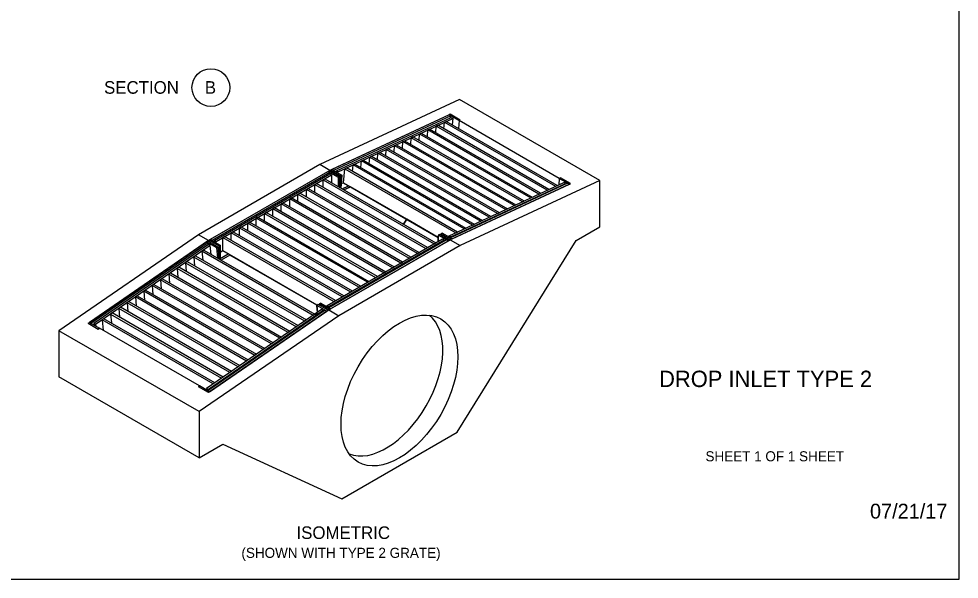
# Model space of a CAD drawing. Extents: x 99862 to 103151, y 100000 to 102076.
# Drawn here: x 101658 to 103151, y 100000 to 100890 of the extents above; entities that cross this region are included whole.
import ezdxf

# ---------------------------------------------------------------- set-up
doc = ezdxf.new("R2010")
doc.units = 0
for name, color, linetype in [('Level 1', 7, 'Continuous'), ('Level 10', 7, 'Continuous'), ('Level 15', 7, 'Continuous'), ('Level 2', 7, 'Continuous'), ('Level 20', 7, 'Continuous'), ('Level 4', 7, 'Continuous'), ('Level 62', 7, 'Continuous'), ('Level 7', 7, 'Continuous'), ('Level 9', 7, 'Continuous')]:
    doc.layers.add(name, color=color, linetype=linetype)

msp = doc.modelspace()

# ---------------------------------------------------------------- linework, layer by layer
at = {"layer": 'Level 1'}
msp.add_lwpolyline([(99862, 99999.5), (103151, 99999.5), (103151, 102075.5), (99862, 102075.5)], close=True, dxfattribs=at)
at = {"layer": 'Level 10'}
for points in [[(102269, 100563.5), (102274, 100571.5), (102184.7, 100623), (102174.3, 100618.1), (102269, 100563.5)], [(102274, 100571.5), (102269, 100563.5), (102320.1, 100534), (102324.1, 100536.3), (102324.1, 100542.5), (102274, 100571.5)], [(102132.1, 100423.4), (102131.2, 100434.5), (102131.4, 100434.7), (101993.3, 100514.4), (101979.2, 100506.3), (102127.9, 100420.5), (102132.1, 100423.4)]]:
    msp.add_lwpolyline(points, dxfattribs=at)
at = {"layer": 'Level 2'}
for p, q in [((102341.2, 100737.3), (102155.1, 100650.4)), ((102343.8, 100735.7), (102157.7, 100648.8)), ((102343.1, 100738.2), (102341.2, 100737.3)), ((102343.8, 100735.7), (102341.2, 100737.3)), ((102359, 100729), (102343.1, 100738.2)), ((102343.6, 100732.9), (102343.8, 100735.7)), ((102357.1, 100728.1), (102359, 100729)), ((102149.1, 100647.3), (101962.1, 100539.3)), ((102151.7, 100645.7), (101964.8, 100537.8)), ((102149.1, 100647.3), (102151.1, 100648.4)), ((102151.7, 100645.7), (102149.1, 100647.3)), ((102151.7, 100643.4), (102151.7, 100645.7)), ((102152.9, 100647.3), (102153.1, 100649.5)), ((102153.1, 100649.5), (102155.1, 100650.4)), ((102157.7, 100648.8), (102155.1, 100650.4)), ((102167, 100639.2), (102165, 100638.1)), ((102171, 100641.2), (102169, 100640.3)), ((102518.1, 100637.1), (102516.2, 100636.2)), ((102171.4, 100619.8), (102181.7, 100624.7)), ((102174.3, 100618.1), (102184.7, 100623)), ((102529.4, 100628.6), (102343.3, 100541.7)), ((102346, 100540.2), (102532.1, 100627)), ((102529.4, 100628.6), (102532.1, 100627)), ((102532.1, 100627), (102534.1, 100628)), ((102330.1, 100549.3), (102328.1, 100548.4)), ((102346, 100540.2), (102330.1, 100549.3)), ((101770.1, 100407.5), (101956.1, 100535.5)), ((101958.8, 100534), (101772.7, 100406)), ((101956.1, 100535.5), (101958.1, 100536.9)), ((101958.8, 100534), (101956.1, 100535.5)), ((101959.1, 100530.8), (101958.8, 100534)), ((101960.1, 100538.2), (101962.1, 100539.3)), ((101960.1, 100535.7), (101960.1, 100538.2)), ((101964.8, 100537.8), (101962.1, 100539.3)), ((102337.3, 100538.6), (102150.4, 100430.6)), ((102153.1, 100429.1), (102340, 100537)), ((102326.1, 100547.4), (102324.1, 100546.2)), ((102342, 100538.2), (102326.1, 100547.4)), ((102337.3, 100538.6), (102340, 100537)), ((102340, 100537), (102342, 100538.2)), ((102343.3, 100541.7), (102346, 100540.2)), ((102346, 100540.2), (102344, 100539.2)), ((101972.1, 100526.3), (101974, 100527.7)), ((101978, 100530.1), (101976.1, 100529)), ((101990.6, 100516), (101978, 100508.7)), ((101978, 100507), (101978, 100508.7)), ((101993.3, 100514.4), (101979.2, 100506.3)), ((102133.1, 100435.9), (102131.2, 100434.5)), ((102149, 100426.7), (102133.1, 100435.9)), ((102135.2, 100437.1), (102137.1, 100438.3)), ((102153.1, 100429.1), (102137.1, 100438.3)), ((102150.4, 100430.6), (102153.1, 100429.1)), ((102151.1, 100427.9), (102153.1, 100429.1)), ((102144.4, 100426.8), (101958.3, 100298.8)), ((101961, 100297.3), (102147.1, 100425.3)), ((102144.4, 100426.8), (102147.1, 100425.3)), ((102147.1, 100425.3), (102149, 100426.7)), ((101768.1, 100406.2), (101770.1, 100407.5)), ((101768.1, 100406.2), (101784, 100397)), ((101772.7, 100406), (101770.1, 100407.5)), ((101770.1, 100407.5), (101786, 100398.3)), ((101784, 100397), (101786, 100398.3)), ((101945.1, 100306.5), (101943.1, 100305.1)), ((101959, 100295.9), (101943.1, 100305.1)), ((101961, 100297.3), (101945.1, 100306.5)), ((101958.3, 100298.8), (101961, 100297.3)), ((101961, 100297.3), (101959, 100295.9))]:
    msp.add_line(p, q, dxfattribs=at)
for points in [[(102341.2, 100737.3), (102357.1, 100728.1), (102356.1, 100715.6)], [(102149.1, 100647.3), (102165, 100638.1), (102165, 100623.5)], [(102151.1, 100648.4), (102167, 100639.2), (102167, 100622.4)], [(102153.1, 100649.5), (102169, 100640.3), (102167.6, 100622)], [(102155.1, 100650.4), (102171, 100641.2), (102169.4, 100621)], [(102534.1, 100628), (102518.1, 100637.1)], [(102516.2, 100636.2), (102515.4, 100626.2)], [(102532.1, 100627), (102516.2, 100636.2)], [(102344, 100539.2), (102328.1, 100548.4), (102327.9, 100546.3)], [(101956.1, 100535.5), (101972.1, 100526.3), (101973.5, 100509.6)], [(101958.1, 100536.9), (101974, 100527.7), (101975.7, 100508.4)], [(101960.1, 100538.2), (101976.1, 100529), (101976.1, 100508.2)], [(101962.1, 100539.3), (101978, 100530.1), (101978, 100507)], [(102340, 100537), (102324.1, 100546.2), (102324.1, 100536.3)], [(102147.1, 100425.3), (102131.2, 100434.5), (102132.1, 100423.4)], [(102151.1, 100427.9), (102135.2, 100437.1), (102135.2, 100434.7)]]:
    msp.add_lwpolyline(points, dxfattribs=at)
at = {"layer": 'Level 4'}
for p, q in [((102162.3, 100648.2), (102344.5, 100733.3)), ((102333.9, 100725.6), (102336.6, 100726.8)), ((102512.9, 100625), (102336.6, 100726.8)), ((102344.5, 100733.3), (102347.1, 100731.7)), ((102306.7, 100702.7), (102307.5, 100713.3)), ((102307.5, 100713.3), (102310.2, 100714.5)), ((102483.9, 100611.5), (102307.5, 100713.3)), ((102486.5, 100612.7), (102310.2, 100714.5)), ((102319.9, 100708.9), (102320.7, 100719.4)), ((102320.7, 100719.4), (102323.4, 100720.7)), ((102497.1, 100617.6), (102320.7, 100719.4)), ((102499.7, 100618.8), (102323.4, 100720.7)), ((102333.1, 100715), (102333.9, 100725.6)), ((102333.9, 100725.6), (102510.3, 100623.8)), ((102280.3, 100690.4), (102281.1, 100700.9)), ((102281.1, 100700.9), (102283.8, 100702.2)), ((102457.5, 100599.1), (102281.1, 100700.9)), ((102460.1, 100600.4), (102283.8, 100702.2)), ((102293.5, 100696.6), (102294.3, 100707.1)), ((102294.3, 100707.1), (102297, 100708.3)), ((102294.3, 100707.1), (102470.7, 100605.3)), ((102297, 100708.3), (102473.3, 100606.5)), ((102240.7, 100671.9), (102241.5, 100682.4)), ((102241.5, 100682.4), (102244.2, 100683.7)), ((102417.9, 100580.6), (102241.5, 100682.4)), ((102244.2, 100683.7), (102420.5, 100581.9)), ((102253.9, 100678.1), (102254.7, 100688.6)), ((102254.7, 100688.6), (102257.4, 100689.8)), ((102254.7, 100688.6), (102431.1, 100586.8)), ((102257.4, 100689.8), (102433.7, 100588)), ((102267.1, 100684.2), (102267.9, 100694.8)), ((102267.9, 100694.8), (102270.6, 100696)), ((102444.3, 100593), (102267.9, 100694.8)), ((102270.6, 100696), (102446.9, 100594.2)), ((102214.3, 100659.6), (102215.2, 100670.1)), ((102215.2, 100670.1), (102217.8, 100671.4)), ((102215.2, 100670.1), (102391.5, 100568.3)), ((102217.8, 100671.4), (102394.1, 100569.6)), ((102227.5, 100665.7), (102228.3, 100676.3)), ((102228.3, 100676.3), (102231, 100677.5)), ((102404.7, 100574.5), (102228.3, 100676.3)), ((102407.3, 100575.7), (102231, 100677.5)), ((102175.6, 100651.6), (102178.2, 100652.9)), ((102354.5, 100551.1), (102178.2, 100652.9)), ((102187.9, 100647.3), (102188.8, 100657.8)), ((102188.8, 100657.8), (102191.4, 100659)), ((102365.1, 100556), (102188.8, 100657.8)), ((102191.4, 100659), (102367.7, 100557.2)), ((102201.1, 100653.4), (102202, 100664)), ((102202, 100664), (102204.6, 100665.2)), ((102378.3, 100562.2), (102202, 100664)), ((102204.6, 100665.2), (102380.9, 100563.4)), ((101968.8, 100537.8), (102151.7, 100643.4)), ((102154.4, 100641.9), (102151.7, 100643.4)), ((102162.2, 100646.3), (102162.3, 100648.2)), ((102165, 100646.7), (102162.3, 100648.2)), ((102164.8, 100644.7), (102165, 100646.7)), ((102173.8, 100629.3), (102175.6, 100651.6)), ((102175.6, 100651.6), (102351.9, 100549.8)), ((102127.9, 100626.6), (102130.5, 100628.1)), ((102127.9, 100614.3), (102127.9, 100626.6)), ((102127.9, 100626.6), (102304.2, 100524.8)), ((102306.8, 100526.3), (102130.5, 100628.1)), ((102141.1, 100634.2), (102143.8, 100635.8)), ((102141.1, 100622), (102141.1, 100634.2)), ((102141.1, 100634.2), (102317.5, 100532.4)), ((102143.8, 100635.8), (102320.1, 100534)), ((102173.8, 100629.3), (102169.9, 100627.5)), ((102173.8, 100629.3), (102324.1, 100542.5)), ((102341.3, 100544.9), (102523.5, 100629.9)), ((102510.3, 100623.8), (102512.9, 100625)), ((102526.1, 100628.4), (102523.5, 100629.9)), ((102101.3, 100611.3), (102104, 100612.8)), ((102101.3, 100599), (102101.3, 100611.3)), ((102101.3, 100611.3), (102277.7, 100509.5)), ((102280.3, 100511), (102104, 100612.8)), ((102114.6, 100618.9), (102117.3, 100620.5)), ((102114.6, 100606.7), (102114.6, 100618.9)), ((102290.9, 100517.1), (102114.6, 100618.9)), ((102117.3, 100620.5), (102293.6, 100518.7)), ((102483.9, 100611.5), (102486.5, 100612.7)), ((102497.1, 100617.6), (102499.7, 100618.8)), ((102074.8, 100596), (102077.5, 100597.5)), ((102074.8, 100583.7), (102074.8, 100596)), ((102251.2, 100494.2), (102074.8, 100596)), ((102077.5, 100597.5), (102253.8, 100495.7)), ((102088.1, 100603.6), (102090.7, 100605.2)), ((102088.1, 100591.4), (102088.1, 100603.6)), ((102264.4, 100501.8), (102088.1, 100603.6)), ((102267.1, 100503.3), (102090.7, 100605.2)), ((102444.3, 100593), (102446.9, 100594.2)), ((102457.5, 100599.1), (102460.1, 100600.4)), ((102470.7, 100605.3), (102473.3, 100606.5)), ((102048.3, 100580.7), (102051, 100582.2)), ((102048.3, 100568.4), (102048.3, 100580.7)), ((102048.3, 100580.7), (102224.6, 100478.8)), ((102227.3, 100480.4), (102051, 100582.2)), ((102061.6, 100588.3), (102064.2, 100589.8)), ((102061.6, 100576.1), (102061.6, 100588.3)), ((102061.6, 100588.3), (102237.9, 100486.5)), ((102064.2, 100589.8), (102240.6, 100488)), ((102417.9, 100580.6), (102420.5, 100581.9)), ((102431.1, 100586.8), (102433.7, 100588)), ((102021.8, 100565.3), (102024.4, 100566.9)), ((102021.8, 100553.1), (102021.8, 100565.3)), ((102198.1, 100463.5), (102021.8, 100565.3)), ((102200.8, 100465.1), (102024.4, 100566.9)), ((102035.1, 100573), (102037.7, 100574.5)), ((102035.1, 100560.8), (102035.1, 100573)), ((102211.4, 100471.2), (102035.1, 100573)), ((102037.7, 100574.5), (102214, 100472.7)), ((102378.3, 100562.2), (102380.9, 100563.4)), ((102391.5, 100568.3), (102394.1, 100569.6)), ((102404.7, 100574.5), (102407.3, 100575.7)), ((101995.3, 100550), (101997.9, 100551.6)), ((101995.3, 100537.8), (101995.3, 100550)), ((102171.6, 100448.2), (101995.3, 100550)), ((102174.3, 100449.8), (101997.9, 100551.6)), ((102008.5, 100557.7), (102011.2, 100559.2)), ((102008.5, 100545.4), (102008.5, 100557.7)), ((102008.5, 100557.7), (102184.9, 100455.9)), ((102011.2, 100559.2), (102187.5, 100457.4)), ((102351.9, 100549.8), (102354.5, 100551.1)), ((102365.1, 100556), (102367.7, 100557.2)), ((101968.8, 100535.5), (101968.8, 100537.8)), ((101968.8, 100537.8), (101971.4, 100536.3)), ((101971.4, 100534), (101971.4, 100536.3)), ((101982, 100542.4), (101984.7, 100543.9)), ((101982, 100542.4), (102158.4, 100440.6)), ((101982, 100521), (101982, 100542.4)), ((102161, 100442.1), (101984.7, 100543.9)), ((102147.7, 100434.5), (102330.7, 100540.1)), ((102317.5, 100532.4), (102320.1, 100534)), ((102330.7, 100540.1), (102333.4, 100538.6)), ((102341.2, 100542.9), (102341.3, 100544.9)), ((102344, 100543.4), (102341.3, 100544.9)), ((102343.9, 100541.9), (102344, 100543.4)), ((102125.3, 100418.7), (101948.9, 100520.5)), ((101951.6, 100522.3), (102127.9, 100420.5)), ((101962.1, 100529.6), (101959.5, 100531.1)), ((101963.3, 100515.5), (101962.1, 100529.6)), ((101982, 100521), (101978, 100518.7)), ((102131.4, 100434.7), (101982, 100521)), ((102290.9, 100517.1), (102293.6, 100518.7)), ((102304.2, 100524.8), (102306.8, 100526.3)), ((101925.2, 100504.2), (102101.5, 100402.4)), ((102112.1, 100409.6), (101935.7, 100511.4)), ((101938.4, 100513.2), (102114.7, 100411.4)), ((102264.4, 100501.8), (102267.1, 100503.3)), ((102277.7, 100509.5), (102280.3, 100511)), ((102085.7, 100391.5), (101909.3, 100493.3)), ((102088.3, 100393.3), (101912, 100495.1)), ((101922.5, 100502.3), (102098.9, 100400.5)), ((102237.9, 100486.5), (102240.6, 100488)), ((102251.2, 100494.2), (102253.8, 100495.7)), ((102059.3, 100373.3), (101882.9, 100475.1)), ((102061.9, 100375.1), (101885.6, 100476.9)), ((102072.5, 100382.4), (101896.1, 100484.2)), ((101898.8, 100486), (102075.1, 100384.2)), ((102224.6, 100478.8), (102227.3, 100480.4)), ((101859.2, 100458.8), (102035.5, 100357)), ((102046.1, 100364.2), (101869.7, 100466)), ((101872.4, 100467.8), (102048.7, 100366)), ((102198.1, 100463.5), (102200.8, 100465.1)), ((102211.4, 100471.2), (102214, 100472.7)), ((102019.7, 100346.1), (101843.3, 100447.9)), ((101846, 100449.7), (102022.3, 100347.9)), ((102032.9, 100355.1), (101856.5, 100457)), ((102171.6, 100448.2), (102174.3, 100449.8)), ((102184.9, 100455.9), (102187.5, 100457.4)), ((101993.3, 100327.9), (101816.9, 100429.7)), ((101995.9, 100329.7), (101819.6, 100431.5)), ((102006.5, 100337), (101830.1, 100438.8)), ((101832.8, 100440.6), (102009.1, 100338.8)), ((102147.7, 100432.2), (102147.7, 100434.5)), ((102147.7, 100434.5), (102150.4, 100432.9)), ((102150.4, 100430.6), (102150.4, 100432.9)), ((102158.4, 100440.6), (102161, 100442.1)), ((101969.5, 100311.6), (101793.2, 100413.4)), ((101803.7, 100420.6), (101980.1, 100318.8)), ((101982.7, 100320.7), (101806.4, 100422.5)), ((102127.9, 100420.5), (102125.3, 100418.7)), ((102138.5, 100427.8), (102141.1, 100426.2)), ((102141.2, 100424.7), (102141.1, 100426.2)), ((101780, 100404.3), (101777.3, 100405.8)), ((101966.9, 100309.8), (101790.5, 100411.6)), ((102101.5, 100402.4), (102098.9, 100400.5)), ((102114.7, 100411.4), (102112.1, 100409.6)), ((102075.1, 100384.2), (102072.5, 100382.4)), ((102088.3, 100393.3), (102085.7, 100391.5)), ((102061.9, 100375.1), (102059.3, 100373.3)), ((102035.5, 100357), (102032.9, 100355.1)), ((102048.7, 100366), (102046.1, 100364.2)), ((102009.1, 100338.8), (102006.5, 100337)), ((102022.3, 100347.9), (102019.7, 100346.1)), ((101995.9, 100329.7), (101993.3, 100327.9)), ((101969.5, 100311.6), (101966.9, 100309.8)), ((101982.7, 100320.7), (101980.1, 100318.8)), ((101956.3, 100302.5), (101959, 100301))]:
    msp.add_line(p, q, dxfattribs=at)
for points in [[(102165, 100646.7), (102347.1, 100731.7), (102346.3, 100721.2)], [(101971.4, 100536.3), (102154.4, 100641.9), (102154.4, 100629.6)], [(102344, 100543.4), (102526.1, 100628.4), (102526, 100627)], [(102150.4, 100432.9), (102333.4, 100538.6), (102333.4, 100536.3)], [(101959.5, 100531.1), (101777.3, 100405.8), (101777.6, 100403.2)], [(101962.1, 100529.6), (101780, 100404.3), (101780.2, 100401.7)], [(101951.6, 100522.3), (101948.9, 100520.5), (101950.1, 100506.4)], [(101925.2, 100504.2), (101922.5, 100502.3), (101923.7, 100488.3)], [(101938.4, 100513.2), (101935.7, 100511.4), (101936.9, 100497.4)], [(101912, 100495.1), (101909.3, 100493.3), (101910.6, 100479.2)], [(101885.6, 100476.9), (101882.9, 100475.1), (101884.2, 100461)], [(101898.8, 100486), (101896.1, 100484.2), (101897.4, 100470.1)], [(101859.2, 100458.8), (101856.5, 100457), (101857.8, 100442.9)], [(101872.4, 100467.8), (101869.7, 100466), (101871, 100452)], [(101846, 100449.7), (101843.3, 100447.9), (101844.6, 100433.8)], [(101819.6, 100431.5), (101816.9, 100429.7), (101818.2, 100415.7)], [(101832.8, 100440.6), (101830.1, 100438.8), (101831.4, 100424.7)], [(101793.2, 100413.4), (101790.5, 100411.6), (101792, 100394.9)], [(101806.4, 100422.5), (101803.7, 100420.6), (101805, 100406.6)], [(102138.5, 100427.8), (101956.3, 100302.5), (101956.6, 100299.9)], [(102141.1, 100426.2), (101959, 100301), (101959.1, 100299.4)]]:
    msp.add_lwpolyline(points, dxfattribs=at)
at = {"layer": 'Level 7'}
for p, q in [((102357.9, 100761.7), (102136.2, 100658.2)), ((102580.6, 100633.1), (102357.9, 100761.7)), ((102341.2, 100737.3), (102152.1, 100649)), ((102357.1, 100728.1), (102341.2, 100737.3)), ((102516.2, 100636.2), (102357.1, 100728.1)), ((102136.2, 100658.2), (101943.2, 100546.8)), ((102152.1, 100649), (102136.2, 100658.2)), ((102152.1, 100649), (101959.1, 100537.6)), ((102532.1, 100627), (102343, 100538.8)), ((102580.6, 100633.1), (102358.9, 100529.6)), ((102580.6, 100559.6), (102580.6, 100633.1)), ((102274, 100571.5), (102269, 100563.5)), ((102542.8, 100537.8), (102580.6, 100559.6)), ((101943.2, 100546.8), (101721.5, 100394.3)), ((101959.1, 100537.6), (101770.1, 100407.5)), ((101959.1, 100537.6), (101943.2, 100546.8)), ((102343, 100538.8), (102150.1, 100427.4)), ((102343, 100538.8), (102358.9, 100529.6)), ((102354.2, 100232.9), (102542.8, 100537.8)), ((102358.9, 100529.6), (102166, 100418.2)), ((102166, 100418.2), (101944.2, 100265.7)), ((102150.1, 100427.4), (101961, 100297.3)), ((102150.1, 100427.4), (102166, 100418.2)), ((101945.1, 100306.5), (101786, 100398.3)), ((101721.5, 100394.3), (101721.5, 100320.8)), ((101944.2, 100265.7), (101721.5, 100394.3)), ((101944.2, 100192.2), (101721.5, 100320.8)), ((101944.2, 100265.7), (101944.2, 100192.2)), ((102170.7, 100127), (102354.2, 100232.9)), ((101944.2, 100192.2), (101982.1, 100214)), ((101982.1, 100214), (102170.7, 100127))]:
    msp.add_line(p, q, dxfattribs=at)
msp.add_ellipse((102262.4, 100299.3), major_axis=(-65.6, -113.7), ratio=0.57735, dxfattribs=at)
msp.add_ellipse((102241.2, 100311.6), major_axis=(63.7, 110.4), ratio=0.57735, start_param=3.218358, end_param=6.20642, dxfattribs=at)
at = {"layer": 'Level 9'}
msp.add_circle((101963, 100780.6), 30, dxfattribs=at)

# ---------------------------------------------------------------- texts
at = {"layer": 'Level 15'}
msp.add_text('07/21/17', height=23.62, dxfattribs=at).set_placement((103009.4, 100095.8))
at = {"layer": 'Level 20'}
for s, height, p in [('SECTION', 20, (101793.4, 100770.8)), ('B', 20, (101953.4, 100770.8)), ('ISOMETRIC', 20, (102098.9, 100063.4)), ('(SHOWN WITH TYPE 2 GRATE)', 16, (102011.5, 100033.4))]:
    msp.add_text(s, height=height, dxfattribs=at).set_placement(p)
at = {"layer": 'Level 62'}
for s, height, p in [('DROP INLET TYPE 2', 26, (102674.6, 100304.8)), ('SHEET 1 OF 1 SHEET', 16, (102748.2, 100186.8))]:
    msp.add_text(s, height=height, dxfattribs=at).set_placement(p)

doc.saveas('drawing.dxf')
